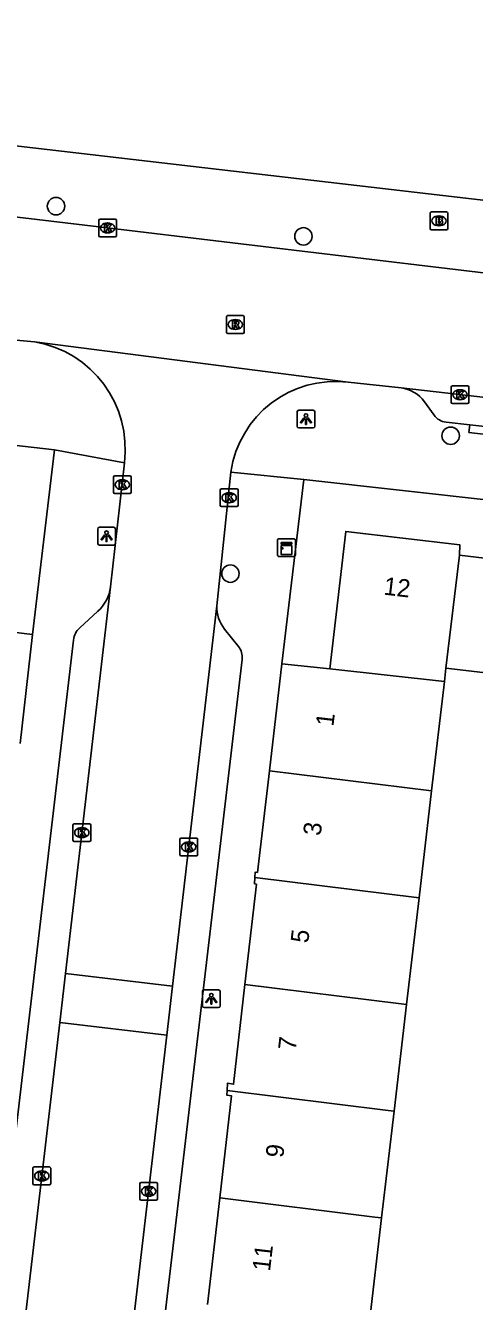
# Model space of a CAD drawing. Extents: x 161243 to 161752, y 384138 to 384885.
# Drawn here: x 161457 to 161482.2, y 384591.8 to 384663.6 of the extents above; entities that cross this region are included whole.
import ezdxf

# ---------------------------------------------------------------- set-up
doc = ezdxf.new("R2010")
doc.units = 0
for name, color, linetype in [('IMGEO_Boom', 7, 'Continuous'), ('IMGEO_Brandkraan', 7, 'Continuous'), ('IMGEO_Kast', 7, 'Continuous'), ('IMGEO_Kolk', 7, 'Continuous'), ('IMGEO_Lichtpunt', 7, 'Continuous'), ('IMGEO_Pand', 7, 'Continuous'), ('IMGEO_Pand_nummerreeks', 7, 'Continuous'), ('IMGEO_Rijbaan_lokaal_open', 7, 'Continuous'), ('IMGEO_Rioolput', 7, 'Continuous'), ('IMGEO_Voetpad_open', 7, 'Continuous')]:
    doc.layers.add(name, color=color, linetype=linetype)

msp = doc.modelspace()

# ---------------------------------------------------------------- linework, layer by layer
at = {"layer": 'IMGEO_Boom'}
for centre in [(161458.672, 384653.424), (161472.581, 384651.726), (161480.857, 384640.508), (161468.474, 384632.749)]:
    msp.add_circle(centre, 0.489, dxfattribs=at)
at = {"layer": 'IMGEO_Brandkraan'}
for p, q in [((161479.696, 384652.172), (161479.696, 384653.024)), ((161479.771, 384653.098), (161480.623, 384653.098)), ((161480.184, 384652.878), (161480.209, 384652.878)), ((161480.697, 384653.024), (161480.697, 384652.172)), ((161480.623, 384652.098), (161479.771, 384652.098)), ((161480.207, 384652.318), (161480.182, 384652.318))]:
    msp.add_line(p, q, dxfattribs=at)
for points in [[(161479.696, 384652.172), (161479.696, 384653.024)], [(161479.771, 384653.098), (161480.623, 384653.098)], [(161480.044, 384652.798), (161480.044, 384652.398), (161480.257, 384652.398)], [(161480.275, 384652.798), (161480.044, 384652.798)], [(161480.697, 384653.024), (161480.697, 384652.172)], [(161480.623, 384652.098), (161479.771, 384652.098)], [(161480.223, 384652.717), (161480.169, 384652.717), (161480.169, 384652.641)], [(161480.169, 384652.641), (161480.222, 384652.641)], [(161480.231, 384652.565), (161480.169, 384652.565), (161480.169, 384652.484)], [(161480.169, 384652.484), (161480.231, 384652.484)]]:
    msp.add_lwpolyline(points, dxfattribs=at)
for centre, radius, start, end in [((161479.773, 384653.022), 0.0765, 91.55205, 178.44795), ((161479.773, 384653.022), 0.0765, 91.55205, 178.44795), ((161480.279, 384652.653), 0.145, 59.4692, 91.53667), ((161480.304, 384652.7), 0.0922, 285.51372, 58.15012), ((161480.621, 384653.022), 0.0765, 1.55205, 88.44795), ((161480.621, 384653.022), 0.0765, 1.55205, 88.44795), ((161479.773, 384652.174), 0.0765, 181.55205, 268.44795), ((161479.773, 384652.174), 0.0765, 181.55205, 268.44795), ((161480.224, 384652.679), 0.0379, 267.82845, 90.93552), ((161480.232, 384652.524), 0.0404, 269.87594, 90.50774), ((161480.263, 384652.649), 0.251, 268.66757, 293.53466), ((161480.309, 384652.508), 0.105, 301.31148, 78.98903), ((161480.621, 384652.174), 0.0765, 271.55205, 358.44795), ((161480.621, 384652.174), 0.0765, 271.55205, 358.44795)]:
    msp.add_arc(centre, radius, start, end, dxfattribs=at)
for centre, major_axis, ratio, start_param, end_param in [((161480.183, 384652.598), (-0.387, 0.002), 0.722429, 4.712389, 7.853982), ((161480.208, 384652.598), (-0.39, 0.002), 0.717154, 1.570796, 4.712389)]:
    msp.add_ellipse(centre, major_axis=major_axis, ratio=ratio, start_param=start_param, end_param=end_param, dxfattribs=at)
at = {"layer": 'IMGEO_Kast'}
for p, q in [((161471.125, 384633.785), (161471.125, 384634.626)), ((161471.125, 384634.626), (161471.125, 384633.785)), ((161471.2, 384634.71), (161472.041, 384634.71)), ((161472.041, 384634.71), (161471.2, 384634.71)), ((161472.125, 384634.635), (161472.125, 384633.794)), ((161472.125, 384633.794), (161472.125, 384634.635)), ((161472.05, 384633.71), (161471.209, 384633.71)), ((161471.209, 384633.71), (161472.05, 384633.71))]:
    msp.add_line(p, q, dxfattribs=at)
for points in [[(161471.32, 384634.5), (161471.92, 384634.5), (161471.92, 384634.415), (161471.32, 384634.415), (161471.32, 384634.5)], [(161471.32, 384634.325), (161471.92, 384634.325), (161471.92, 384633.836), (161471.32, 384633.836), (161471.32, 384634.325)]]:
    msp.add_lwpolyline(points, dxfattribs=at)
msp.add_circle((161471.404, 384634.174), 0.0377, dxfattribs=at)
for centre, start, end in [((161471.203, 384634.632), 92.4484, 184.28452), ((161471.203, 384634.632), 92.4484, 184.28452), ((161472.047, 384634.632), 2.4484, 94.28452), ((161472.047, 384634.632), 2.4484, 94.28452), ((161471.203, 384633.788), 182.4484, 274.28452), ((161471.203, 384633.788), 182.4484, 274.28452), ((161472.047, 384633.788), 272.4484, 4.28452), ((161472.047, 384633.788), 272.4484, 4.28452)]:
    msp.add_arc(centre, 0.0779, start, end, dxfattribs=at)
at = {"layer": 'IMGEO_Kolk'}
for p, q in [((161461.07, 384651.771), (161461.07, 384652.623)), ((161461.145, 384652.697), (161461.997, 384652.697)), ((161461.558, 384652.477), (161461.583, 384652.477)), ((161462.071, 384652.623), (161462.071, 384651.771)), ((161461.997, 384651.697), (161461.145, 384651.697)), ((161461.581, 384651.917), (161461.556, 384651.917)), ((161480.881, 384642.391), (161480.881, 384643.243)), ((161480.956, 384643.317), (161481.808, 384643.317)), ((161481.369, 384643.097), (161481.394, 384643.097)), ((161481.882, 384643.243), (161481.882, 384642.391)), ((161481.808, 384642.317), (161480.956, 384642.317)), ((161481.392, 384642.537), (161481.367, 384642.537)), ((161461.895, 384637.325), (161461.895, 384638.177)), ((161461.97, 384638.251), (161462.822, 384638.251)), ((161462.383, 384638.031), (161462.408, 384638.031)), ((161462.896, 384638.177), (161462.896, 384637.325)), ((161462.822, 384637.251), (161461.97, 384637.251)), ((161462.406, 384637.471), (161462.381, 384637.471)), ((161467.904, 384636.595), (161467.904, 384637.447)), ((161467.979, 384637.521), (161468.831, 384637.521)), ((161468.392, 384637.301), (161468.417, 384637.301)), ((161468.905, 384637.447), (161468.905, 384636.595)), ((161468.831, 384636.521), (161467.979, 384636.521)), ((161468.415, 384636.741), (161468.39, 384636.741)), ((161459.623, 384617.755), (161459.623, 384618.607)), ((161459.698, 384618.681), (161460.55, 384618.681)), ((161460.111, 384618.461), (161460.136, 384618.461)), ((161460.624, 384618.607), (161460.624, 384617.755)), ((161460.55, 384617.681), (161459.698, 384617.681)), ((161460.134, 384617.901), (161460.109, 384617.901)), ((161465.633, 384616.95), (161465.633, 384617.802)), ((161465.708, 384617.876), (161466.56, 384617.876)), ((161466.121, 384617.656), (161466.146, 384617.656)), ((161466.634, 384617.802), (161466.634, 384616.95)), ((161466.56, 384616.876), (161465.708, 384616.876)), ((161466.144, 384617.096), (161466.119, 384617.096)), ((161457.372, 384598.442), (161457.372, 384599.294)), ((161457.447, 384599.368), (161458.299, 384599.368)), ((161457.86, 384599.148), (161457.885, 384599.148)), ((161458.373, 384599.294), (161458.373, 384598.442)), ((161458.299, 384598.368), (161457.447, 384598.368)), ((161457.883, 384598.588), (161457.858, 384598.588)), ((161463.376, 384597.576), (161463.376, 384598.428)), ((161463.451, 384598.502), (161464.303, 384598.502)), ((161463.864, 384598.282), (161463.889, 384598.282)), ((161464.377, 384598.428), (161464.377, 384597.576)), ((161464.303, 384597.502), (161463.451, 384597.502)), ((161463.887, 384597.722), (161463.862, 384597.722))]:
    msp.add_line(p, q, dxfattribs=at)
for points in [[(161461.07, 384651.771), (161461.07, 384652.623)], [(161461.145, 384652.697), (161461.997, 384652.697)], [(161461.391, 384652.397), (161461.514, 384652.397), (161461.514, 384652.246), (161461.644, 384652.397), (161461.808, 384652.397), (161461.662, 384652.246), (161461.815, 384651.997), (161461.663, 384651.997), (161461.578, 384652.161), (161461.514, 384652.094), (161461.514, 384651.997), (161461.391, 384651.997), (161461.391, 384652.397)], [(161462.071, 384652.623), (161462.071, 384651.771)], [(161461.997, 384651.697), (161461.145, 384651.697)], [(161480.881, 384642.391), (161480.881, 384643.243)], [(161480.956, 384643.317), (161481.808, 384643.317)], [(161481.202, 384643.017), (161481.325, 384643.017), (161481.325, 384642.866), (161481.455, 384643.017), (161481.619, 384643.017), (161481.473, 384642.866), (161481.626, 384642.617), (161481.474, 384642.617), (161481.389, 384642.781), (161481.325, 384642.714), (161481.325, 384642.617), (161481.202, 384642.617), (161481.202, 384643.017)], [(161481.882, 384643.243), (161481.882, 384642.391)], [(161481.808, 384642.317), (161480.956, 384642.317)], [(161461.895, 384637.325), (161461.895, 384638.177)], [(161461.97, 384638.251), (161462.822, 384638.251)], [(161462.216, 384637.951), (161462.339, 384637.951), (161462.339, 384637.8), (161462.469, 384637.951), (161462.633, 384637.951), (161462.487, 384637.8), (161462.64, 384637.551), (161462.488, 384637.551), (161462.403, 384637.715), (161462.339, 384637.648), (161462.339, 384637.551), (161462.216, 384637.551), (161462.216, 384637.951)], [(161462.896, 384638.177), (161462.896, 384637.325)], [(161462.822, 384637.251), (161461.97, 384637.251)], [(161467.904, 384636.595), (161467.904, 384637.447)], [(161467.979, 384637.521), (161468.831, 384637.521)], [(161468.225, 384637.221), (161468.348, 384637.221), (161468.348, 384637.07), (161468.478, 384637.221), (161468.642, 384637.221), (161468.496, 384637.07), (161468.649, 384636.821), (161468.497, 384636.821), (161468.412, 384636.985), (161468.348, 384636.918), (161468.348, 384636.821), (161468.225, 384636.821), (161468.225, 384637.221)], [(161468.905, 384637.447), (161468.905, 384636.595)], [(161468.831, 384636.521), (161467.979, 384636.521)], [(161459.623, 384617.755), (161459.623, 384618.607)], [(161459.698, 384618.681), (161460.55, 384618.681)], [(161459.944, 384618.381), (161460.067, 384618.381), (161460.067, 384618.23), (161460.197, 384618.381), (161460.361, 384618.381), (161460.215, 384618.23), (161460.368, 384617.981), (161460.216, 384617.981), (161460.131, 384618.145), (161460.067, 384618.078), (161460.067, 384617.981), (161459.944, 384617.981), (161459.944, 384618.381)], [(161460.624, 384618.607), (161460.624, 384617.755)], [(161460.55, 384617.681), (161459.698, 384617.681)], [(161465.633, 384616.95), (161465.633, 384617.802)], [(161465.708, 384617.876), (161466.56, 384617.876)], [(161465.954, 384617.576), (161466.077, 384617.576), (161466.077, 384617.425), (161466.207, 384617.576), (161466.371, 384617.576), (161466.225, 384617.425), (161466.378, 384617.176), (161466.226, 384617.176), (161466.141, 384617.34), (161466.077, 384617.273), (161466.077, 384617.176), (161465.954, 384617.176), (161465.954, 384617.576)], [(161466.634, 384617.802), (161466.634, 384616.95)], [(161466.56, 384616.876), (161465.708, 384616.876)], [(161457.372, 384598.442), (161457.372, 384599.294)], [(161457.447, 384599.368), (161458.299, 384599.368)], [(161457.693, 384599.068), (161457.816, 384599.068), (161457.816, 384598.917), (161457.946, 384599.068), (161458.11, 384599.068), (161457.964, 384598.917), (161458.117, 384598.668), (161457.965, 384598.668), (161457.88, 384598.832), (161457.816, 384598.765), (161457.816, 384598.668), (161457.693, 384598.668), (161457.693, 384599.068)], [(161458.373, 384599.294), (161458.373, 384598.442)], [(161458.299, 384598.368), (161457.447, 384598.368)], [(161463.376, 384597.576), (161463.376, 384598.428)], [(161463.451, 384598.502), (161464.303, 384598.502)], [(161463.697, 384598.202), (161463.82, 384598.202), (161463.82, 384598.051), (161463.95, 384598.202), (161464.114, 384598.202), (161463.968, 384598.051), (161464.121, 384597.802), (161463.969, 384597.802), (161463.884, 384597.966), (161463.82, 384597.899), (161463.82, 384597.802), (161463.697, 384597.802), (161463.697, 384598.202)], [(161464.377, 384598.428), (161464.377, 384597.576)], [(161464.303, 384597.502), (161463.451, 384597.502)]]:
    msp.add_lwpolyline(points, dxfattribs=at)
for centre, start, end in [((161461.147, 384652.621), 91.55205, 178.44795), ((161461.147, 384652.621), 91.55205, 178.44795), ((161461.995, 384652.621), 1.55205, 88.44795), ((161461.995, 384652.621), 1.55205, 88.44795), ((161461.147, 384651.773), 181.55205, 268.44795), ((161461.147, 384651.773), 181.55205, 268.44795), ((161461.995, 384651.773), 271.55205, 358.44795), ((161461.995, 384651.773), 271.55205, 358.44795), ((161480.958, 384643.241), 91.55205, 178.44795), ((161480.958, 384643.241), 91.55205, 178.44795), ((161481.806, 384643.241), 1.55205, 88.44795), ((161481.806, 384643.241), 1.55205, 88.44795), ((161480.958, 384642.393), 181.55205, 268.44795), ((161480.958, 384642.393), 181.55205, 268.44795), ((161481.806, 384642.393), 271.55205, 358.44795), ((161481.806, 384642.393), 271.55205, 358.44795), ((161461.972, 384638.175), 91.55205, 178.44795), ((161461.972, 384638.175), 91.55205, 178.44795), ((161462.82, 384638.175), 1.55205, 88.44795), ((161462.82, 384638.175), 1.55205, 88.44795), ((161461.972, 384637.327), 181.55205, 268.44795), ((161461.972, 384637.327), 181.55205, 268.44795), ((161462.82, 384637.327), 271.55205, 358.44795), ((161462.82, 384637.327), 271.55205, 358.44795), ((161467.981, 384637.445), 91.55205, 178.44795), ((161467.981, 384637.445), 91.55205, 178.44795), ((161468.829, 384637.445), 1.55205, 88.44795), ((161468.829, 384637.445), 1.55205, 88.44795), ((161467.981, 384636.597), 181.55205, 268.44795), ((161467.981, 384636.597), 181.55205, 268.44795), ((161468.829, 384636.597), 271.55205, 358.44795), ((161468.829, 384636.597), 271.55205, 358.44795), ((161459.7, 384618.605), 91.55205, 178.44795), ((161459.7, 384618.605), 91.55205, 178.44795), ((161460.548, 384618.605), 1.55205, 88.44795), ((161460.548, 384618.605), 1.55205, 88.44795), ((161459.7, 384617.757), 181.55205, 268.44795), ((161459.7, 384617.757), 181.55205, 268.44795), ((161460.548, 384617.757), 271.55205, 358.44795), ((161460.548, 384617.757), 271.55205, 358.44795), ((161465.71, 384617.8), 91.55205, 178.44795), ((161465.71, 384617.8), 91.55205, 178.44795), ((161466.558, 384617.8), 1.55205, 88.44795), ((161466.558, 384617.8), 1.55205, 88.44795), ((161465.71, 384616.952), 181.55205, 268.44795), ((161465.71, 384616.952), 181.55205, 268.44795), ((161466.558, 384616.952), 271.55205, 358.44795), ((161466.558, 384616.952), 271.55205, 358.44795), ((161457.449, 384599.292), 91.55205, 178.44795), ((161457.449, 384599.292), 91.55205, 178.44795), ((161458.297, 384599.292), 1.55205, 88.44795), ((161458.297, 384599.292), 1.55205, 88.44795), ((161457.449, 384598.444), 181.55205, 268.44795), ((161457.449, 384598.444), 181.55205, 268.44795), ((161458.297, 384598.444), 271.55205, 358.44795), ((161458.297, 384598.444), 271.55205, 358.44795), ((161463.453, 384598.426), 91.55205, 178.44795), ((161463.453, 384598.426), 91.55205, 178.44795), ((161464.301, 384598.426), 1.55205, 88.44795), ((161464.301, 384598.426), 1.55205, 88.44795), ((161463.453, 384597.578), 181.55205, 268.44795), ((161463.453, 384597.578), 181.55205, 268.44795), ((161464.301, 384597.578), 271.55205, 358.44795), ((161464.301, 384597.578), 271.55205, 358.44795)]:
    msp.add_arc(centre, 0.0765, start, end, dxfattribs=at)
for centre, major_axis, ratio, start_param, end_param in [((161461.557, 384652.197), (-0.387, 0.002), 0.722429, 4.712389, 7.853982), ((161461.582, 384652.197), (-0.39, 0.002), 0.717154, 1.570796, 4.712389), ((161481.368, 384642.817), (-0.387, 0.002), 0.722429, 4.712389, 7.853982), ((161481.393, 384642.817), (-0.39, 0.002), 0.717154, 1.570796, 4.712389), ((161462.382, 384637.751), (-0.387, 0.002), 0.722429, 4.712389, 7.853982), ((161462.407, 384637.751), (-0.39, 0.002), 0.717154, 1.570796, 4.712389), ((161468.391, 384637.021), (-0.387, 0.002), 0.722429, 4.712389, 7.853982), ((161468.416, 384637.021), (-0.39, 0.002), 0.717154, 1.570796, 4.712389), ((161460.11, 384618.181), (-0.387, 0.002), 0.722429, 4.712389, 7.853982), ((161460.135, 384618.181), (-0.39, 0.002), 0.717154, 1.570796, 4.712389), ((161466.12, 384617.376), (-0.387, 0.002), 0.722429, 4.712389, 7.853982), ((161466.145, 384617.376), (-0.39, 0.002), 0.717154, 1.570796, 4.712389), ((161457.859, 384598.868), (-0.387, 0.002), 0.722429, 4.712389, 7.853982), ((161457.884, 384598.868), (-0.39, 0.002), 0.717154, 1.570796, 4.712389), ((161463.863, 384598.002), (-0.387, 0.002), 0.722429, 4.712389, 7.853982), ((161463.888, 384598.002), (-0.39, 0.002), 0.717154, 1.570796, 4.712389)]:
    msp.add_ellipse(centre, major_axis=major_axis, ratio=ratio, start_param=start_param, end_param=end_param, dxfattribs=at)
at = {"layer": 'IMGEO_Lichtpunt'}
for p, q in [((161472.225, 384641.847), (161472.225, 384641.04)), ((161472.225, 384641.847), (161472.225, 384641.04)), ((161473.127, 384641.942), (161472.319, 384641.942)), ((161473.127, 384641.942), (161472.319, 384641.942)), ((161473.221, 384641.04), (161473.221, 384641.847)), ((161473.221, 384641.04), (161473.221, 384641.847)), ((161472.319, 384640.946), (161473.127, 384640.946)), ((161472.319, 384640.946), (161473.127, 384640.946)), ((161461.014, 384635.261), (161461.014, 384634.454)), ((161461.014, 384635.261), (161461.014, 384634.454)), ((161461.916, 384635.356), (161461.108, 384635.356)), ((161461.916, 384635.356), (161461.108, 384635.356)), ((161462.01, 384634.454), (161462.01, 384635.261)), ((161462.01, 384634.454), (161462.01, 384635.261)), ((161461.108, 384634.36), (161461.916, 384634.36)), ((161461.108, 384634.36), (161461.916, 384634.36)), ((161466.903, 384609.24), (161466.903, 384608.433)), ((161466.903, 384609.24), (161466.903, 384608.433)), ((161467.805, 384609.335), (161466.997, 384609.335)), ((161467.805, 384609.335), (161466.997, 384609.335)), ((161467.899, 384608.433), (161467.899, 384609.24)), ((161467.899, 384608.433), (161467.899, 384609.24)), ((161466.997, 384608.339), (161467.805, 384608.339)), ((161466.997, 384608.339), (161467.805, 384608.339))]:
    msp.add_line(p, q, dxfattribs=at)
for points in [[(161472.599, 384641.511), (161472.638, 384641.483), (161472.45, 384641.221), (161472.412, 384641.248), (161472.599, 384641.511)], [(161472.701, 384641.463), (161472.748, 384641.463), (161472.748, 384641.141), (161472.701, 384641.141), (161472.701, 384641.463)], [(161472.811, 384641.483), (161472.849, 384641.51), (161473.036, 384641.248), (161472.997, 384641.22), (161472.811, 384641.483)], [(161461.388, 384634.925), (161461.427, 384634.897), (161461.239, 384634.635), (161461.201, 384634.662), (161461.388, 384634.925)], [(161461.49, 384634.877), (161461.537, 384634.877), (161461.537, 384634.555), (161461.49, 384634.555), (161461.49, 384634.877)], [(161461.6, 384634.897), (161461.638, 384634.924), (161461.825, 384634.662), (161461.786, 384634.634), (161461.6, 384634.897)], [(161467.277, 384608.904), (161467.316, 384608.876), (161467.128, 384608.614), (161467.09, 384608.641), (161467.277, 384608.904)], [(161467.379, 384608.856), (161467.426, 384608.856), (161467.426, 384608.534), (161467.379, 384608.534), (161467.379, 384608.856)], [(161467.489, 384608.876), (161467.527, 384608.903), (161467.714, 384608.641), (161467.675, 384608.613), (161467.489, 384608.876)]]:
    msp.add_lwpolyline(points, dxfattribs=at)
for centre in [(161472.724, 384641.645), (161461.513, 384635.059), (161467.402, 384609.038)]:
    msp.add_circle(centre, 0.0994, dxfattribs=at)
for centre, start, end in [((161472.319, 384641.847), 90, 180), ((161472.319, 384641.847), 90, 180), ((161473.127, 384641.847), 0, 90), ((161473.127, 384641.847), 0, 90), ((161472.319, 384641.04), 180, 270), ((161472.319, 384641.04), 180, 270), ((161473.127, 384641.04), 270, 0), ((161473.127, 384641.04), 270, 360), ((161461.108, 384635.261), 90, 180), ((161461.108, 384635.261), 90, 180), ((161461.916, 384635.261), 0, 90), ((161461.916, 384635.261), 0, 90), ((161461.108, 384634.454), 180, 270), ((161461.108, 384634.454), 180, 270), ((161461.916, 384634.454), 270, 0), ((161461.916, 384634.454), 270, 360), ((161466.997, 384609.24), 90, 180), ((161466.997, 384609.24), 90, 180), ((161467.805, 384609.24), 0, 90), ((161467.805, 384609.24), 0, 90), ((161466.997, 384608.433), 180, 270), ((161466.997, 384608.433), 180, 270), ((161467.805, 384608.433), 270, 0), ((161467.805, 384608.433), 270, 360)]:
    msp.add_arc(centre, 0.0946, start, end, dxfattribs=at)
at = {"layer": 'IMGEO_Pand'}
for points in [[(161474.064, 384627.391), (161474.958, 384635.124), (161481.38, 384634.367), (161481.361, 384633.795)], [(161481.361, 384633.795), (161490.094, 384632.743), (161490.303, 384634.456), (161496.436, 384633.757)], [(161480.594, 384627.428), (161481.361, 384633.795)], [(161454.687, 384629.637), (161457.357, 384629.317)], [(161457.357, 384629.317), (161456.659, 384623.201)], [(161470.664, 384621.655), (161471.374, 384627.684)], [(161471.374, 384627.684), (161474.064, 384627.391)], [(161474.064, 384627.391), (161480.507, 384626.683)], [(161480.594, 384627.428), (161480.507, 384626.683)], [(161495.324, 384624.779), (161489.259, 384625.489), (161489.365, 384626.402), (161480.594, 384627.428)], [(161480.507, 384626.683), (161479.786, 384620.526)], [(161469.852, 384615.663), (161469.867, 384615.956), (161469.99, 384615.939), (161470.664, 384621.655)], [(161470.664, 384621.655), (161479.786, 384620.526)], [(161479.786, 384620.526), (161479.083, 384614.52)], [(161469.293, 384609.641), (161469.934, 384615.273), (161469.834, 384615.308), (161469.852, 384615.663)], [(161479.083, 384614.52), (161469.852, 384615.663)], [(161479.083, 384614.52), (161478.38, 384608.515)], [(161468.285, 384603.673), (161468.309, 384604.077), (161468.654, 384604.025), (161469.293, 384609.641)], [(161478.38, 384608.515), (161478.081, 384608.552), (161469.293, 384609.641)], [(161478.38, 384608.515), (161477.677, 384602.51)], [(161467.872, 384597.633), (161468.535, 384603.372), (161468.27, 384603.414), (161468.285, 384603.673)], [(161477.677, 384602.51), (161477.338, 384602.552), (161468.285, 384603.673)], [(161477.677, 384602.51), (161476.974, 384596.505)], [(161467.179, 384591.626), (161467.872, 384597.633)], [(161467.872, 384597.633), (161476.595, 384596.552), (161476.974, 384596.505)], [(161476.974, 384596.505), (161476.271, 384590.5)]]:
    msp.add_lwpolyline(points, dxfattribs=at)
at = {"layer": 'IMGEO_Rijbaan_lokaal_open'}
for points in [[(161492.527, 384648.513), (161488.024, 384649.043), (161468.593, 384651.357), (161461.074, 384652.254), (161448.451, 384653.761), (161437.269, 384655.04)], [(161453.111, 384646.178), (161457.465, 384645.799)], [(161475.102, 384643.523), (161457.465, 384645.799)], [(161475.102, 384643.523), (161478.073, 384643.196)], [(161478.073, 384643.196), (161500, 384640.692), (161518.762, 384638.682)], [(161462.513, 384638.982), (161461.735, 384631.999)], [(161467.711, 384630.934), (161468.506, 384638.465)], [(161461.735, 384631.999), (161459.201, 384610.247)], [(161465.22, 384609.545), (161467.711, 384630.934)], [(161459.201, 384610.247), (161458.88, 384607.496)], [(161459.201, 384610.247), (161465.22, 384609.545)], [(161465.22, 384609.545), (161464.9, 384606.794)], [(161458.88, 384607.496), (161456.155, 384584.108)], [(161458.88, 384607.496), (161464.9, 384606.794)], [(161464.9, 384606.794), (161462.171, 384583.365)]]:
    msp.add_lwpolyline(points, dxfattribs=at)
for centre, radius, start, end in [((161456.428, 384639.754), 6.133, 352.76968, 80.27035), ((161474.388, 384637.624), 5.942, 83.10095, 171.86307)]:
    msp.add_arc(centre, radius, start, end, dxfattribs=at)
at = {"layer": 'IMGEO_Rioolput'}
for p, q in [((161468.252, 384646.34), (161468.252, 384647.192)), ((161468.327, 384647.266), (161469.179, 384647.266)), ((161468.74, 384647.046), (161468.765, 384647.046)), ((161469.253, 384647.192), (161469.253, 384646.34)), ((161468.763, 384646.486), (161468.738, 384646.486)), ((161469.179, 384646.266), (161468.327, 384646.266))]:
    msp.add_line(p, q, dxfattribs=at)
for points in [[(161468.252, 384646.34), (161468.252, 384647.192)], [(161468.327, 384647.266), (161469.179, 384647.266)], [(161469.253, 384647.192), (161469.253, 384646.34)], [(161468.841, 384646.964), (161468.589, 384646.966), (161468.589, 384646.566)], [(161468.589, 384646.566), (161468.713, 384646.566), (161468.713, 384646.728), (161468.724, 384646.728)], [(161468.767, 384646.885), (161468.713, 384646.885), (161468.713, 384646.804)], [(161468.713, 384646.804), (161468.765, 384646.804)], [(161468.771, 384646.699), (161468.842, 384646.566), (161468.982, 384646.566), (161468.917, 384646.692)], [(161469.179, 384646.266), (161468.327, 384646.266)]]:
    msp.add_lwpolyline(points, dxfattribs=at)
for centre, radius, start, end in [((161468.329, 384647.19), 0.0765, 91.55205, 178.44795), ((161468.329, 384647.19), 0.0765, 91.55205, 178.44795), ((161469.177, 384647.19), 0.0765, 1.55205, 88.44795), ((161469.177, 384647.19), 0.0765, 1.55205, 88.44795), ((161468.329, 384646.342), 0.0765, 181.55205, 268.44795), ((161468.329, 384646.342), 0.0765, 181.55205, 268.44795), ((161468.723, 384646.675), 0.0533, 26.02933, 88.69889), ((161468.749, 384646.993), 0.19, 274.7715, 282.96867), ((161468.773, 384646.789), 0.0964, 77.00612, 93.18647), ((161468.787, 384646.846), 0.0378, 276.66336, 79.67722), ((161468.84, 384646.854), 0.109, 350.36119, 89.41601), ((161468.838, 384646.854), 0.112, 277.58423, 350.98172), ((161468.822, 384646.639), 0.108, 29.51342, 73.79051), ((161469.177, 384646.342), 0.0765, 271.55205, 358.44795), ((161469.177, 384646.342), 0.0765, 271.55205, 358.44795)]:
    msp.add_arc(centre, radius, start, end, dxfattribs=at)
for centre, major_axis, ratio, start_param, end_param in [((161468.739, 384646.766), (-0.387, 0.002), 0.722429, 4.712389, 7.853982), ((161468.764, 384646.766), (-0.39, 0.002), 0.717154, 1.570796, 4.712389)]:
    msp.add_ellipse(centre, major_axis=major_axis, ratio=ratio, start_param=start_param, end_param=end_param, dxfattribs=at)
at = {"layer": 'IMGEO_Voetpad_open'}
for points in [[(161492.983, 384652.558), (161398.187, 384663.587)], [(161458.589, 384639.718), (161400.088, 384646.416)], [(161479.932, 384641.661), (161479.383, 384642.423)], [(161481.929, 384641.123), (161480.6, 384641.271)], [(161491.025, 384640.113), (161490.978, 384639.644), (161481.88, 384640.693), (161481.929, 384641.123)], [(161481.929, 384641.123), (161491.025, 384640.113)], [(161458.589, 384639.718), (161457.357, 384629.317)], [(161462.513, 384638.982), (161458.589, 384639.718)], [(161468.506, 384638.465), (161472.604, 384638.05)], [(161472.604, 384638.05), (161471.374, 384627.684)], [(161472.604, 384638.05), (161500, 384634.982), (161522.66, 384632.445)], [(161460.001, 384629.696), (161461.027, 384630.63)], [(161468.145, 384629.632), (161468.925, 384628.66)], [(161454.735, 384587.127), (161459.649, 384629.015)], [(161469.135, 384627.927), (161464.207, 384586.016)]]:
    msp.add_lwpolyline(points, dxfattribs=at)
for centre, radius, start, end in [((161477.842, 384641.309), 1.901, 35.87922, 83.03308), ((161480.705, 384642.218), 0.953, 215.78483, 263.65964), ((161459.537, 384632.268), 2.214, 312.28702, 353.02006), ((161469.666, 384630.862), 1.957, 177.90426, 218.96564), ((161460.745, 384628.88), 1.104, 132.35675, 172.97554), ((161468.16, 384628.044), 0.982, 353.13262, 38.84075)]:
    msp.add_arc(centre, radius, start, end, dxfattribs=at)

# ---------------------------------------------------------------- texts
at = {"layer": 'IMGEO_Pand_nummerreeks'}
for s, rotation, p in [('12', 353.27722, (161477.052, 384631.575)), ('1', 83.37125, (161474.263, 384624.125)), ('3', 83.37125, (161473.548, 384617.972)), ('5', 83.37125, (161472.846, 384611.933)), ('7', 83.37125, (161472.144, 384605.893)), ('9', 83.37125, (161471.442, 384599.854)), ('11', 83.37125, (161470.7, 384593.471))]:
    msp.add_text(s, height=1, rotation=rotation, dxfattribs=at).set_placement(p)

doc.saveas('drawing.dxf')
